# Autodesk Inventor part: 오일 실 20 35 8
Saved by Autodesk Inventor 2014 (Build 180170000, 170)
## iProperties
Created: 2026-04
Part Number: 오일 실 20 35 8
Material: 일반
Document SubType Name: Modeling
Designer: dg
Density: 1 g/cm^3
Appearance: 기본값
Author: dg
Author: jhkim
Description: 오일-실
Creation Date: 2026-03-26
Sending System: Autodesk Inventor 2026
Preprocessor: ST-DEVELOPER v20.1
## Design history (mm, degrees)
node "오일 실 20 35 81"
body "Solid1"
node "기준1"
